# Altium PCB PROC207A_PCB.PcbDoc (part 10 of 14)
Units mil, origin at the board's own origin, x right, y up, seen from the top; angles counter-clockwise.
Board outline 4094.49 x 3724.79 mil, 8 copper layers (Top Layer, L2_GND1, L3_SIG1, L4_PWR1, L5_PWR2, L6_SIG2, L7_GND2, Bottom Layer), stack 58.1 mil thick; 584 components, 399 nets, 8440 pads, 5258 vias.
Unrouted connection lines stored in the file: 9.
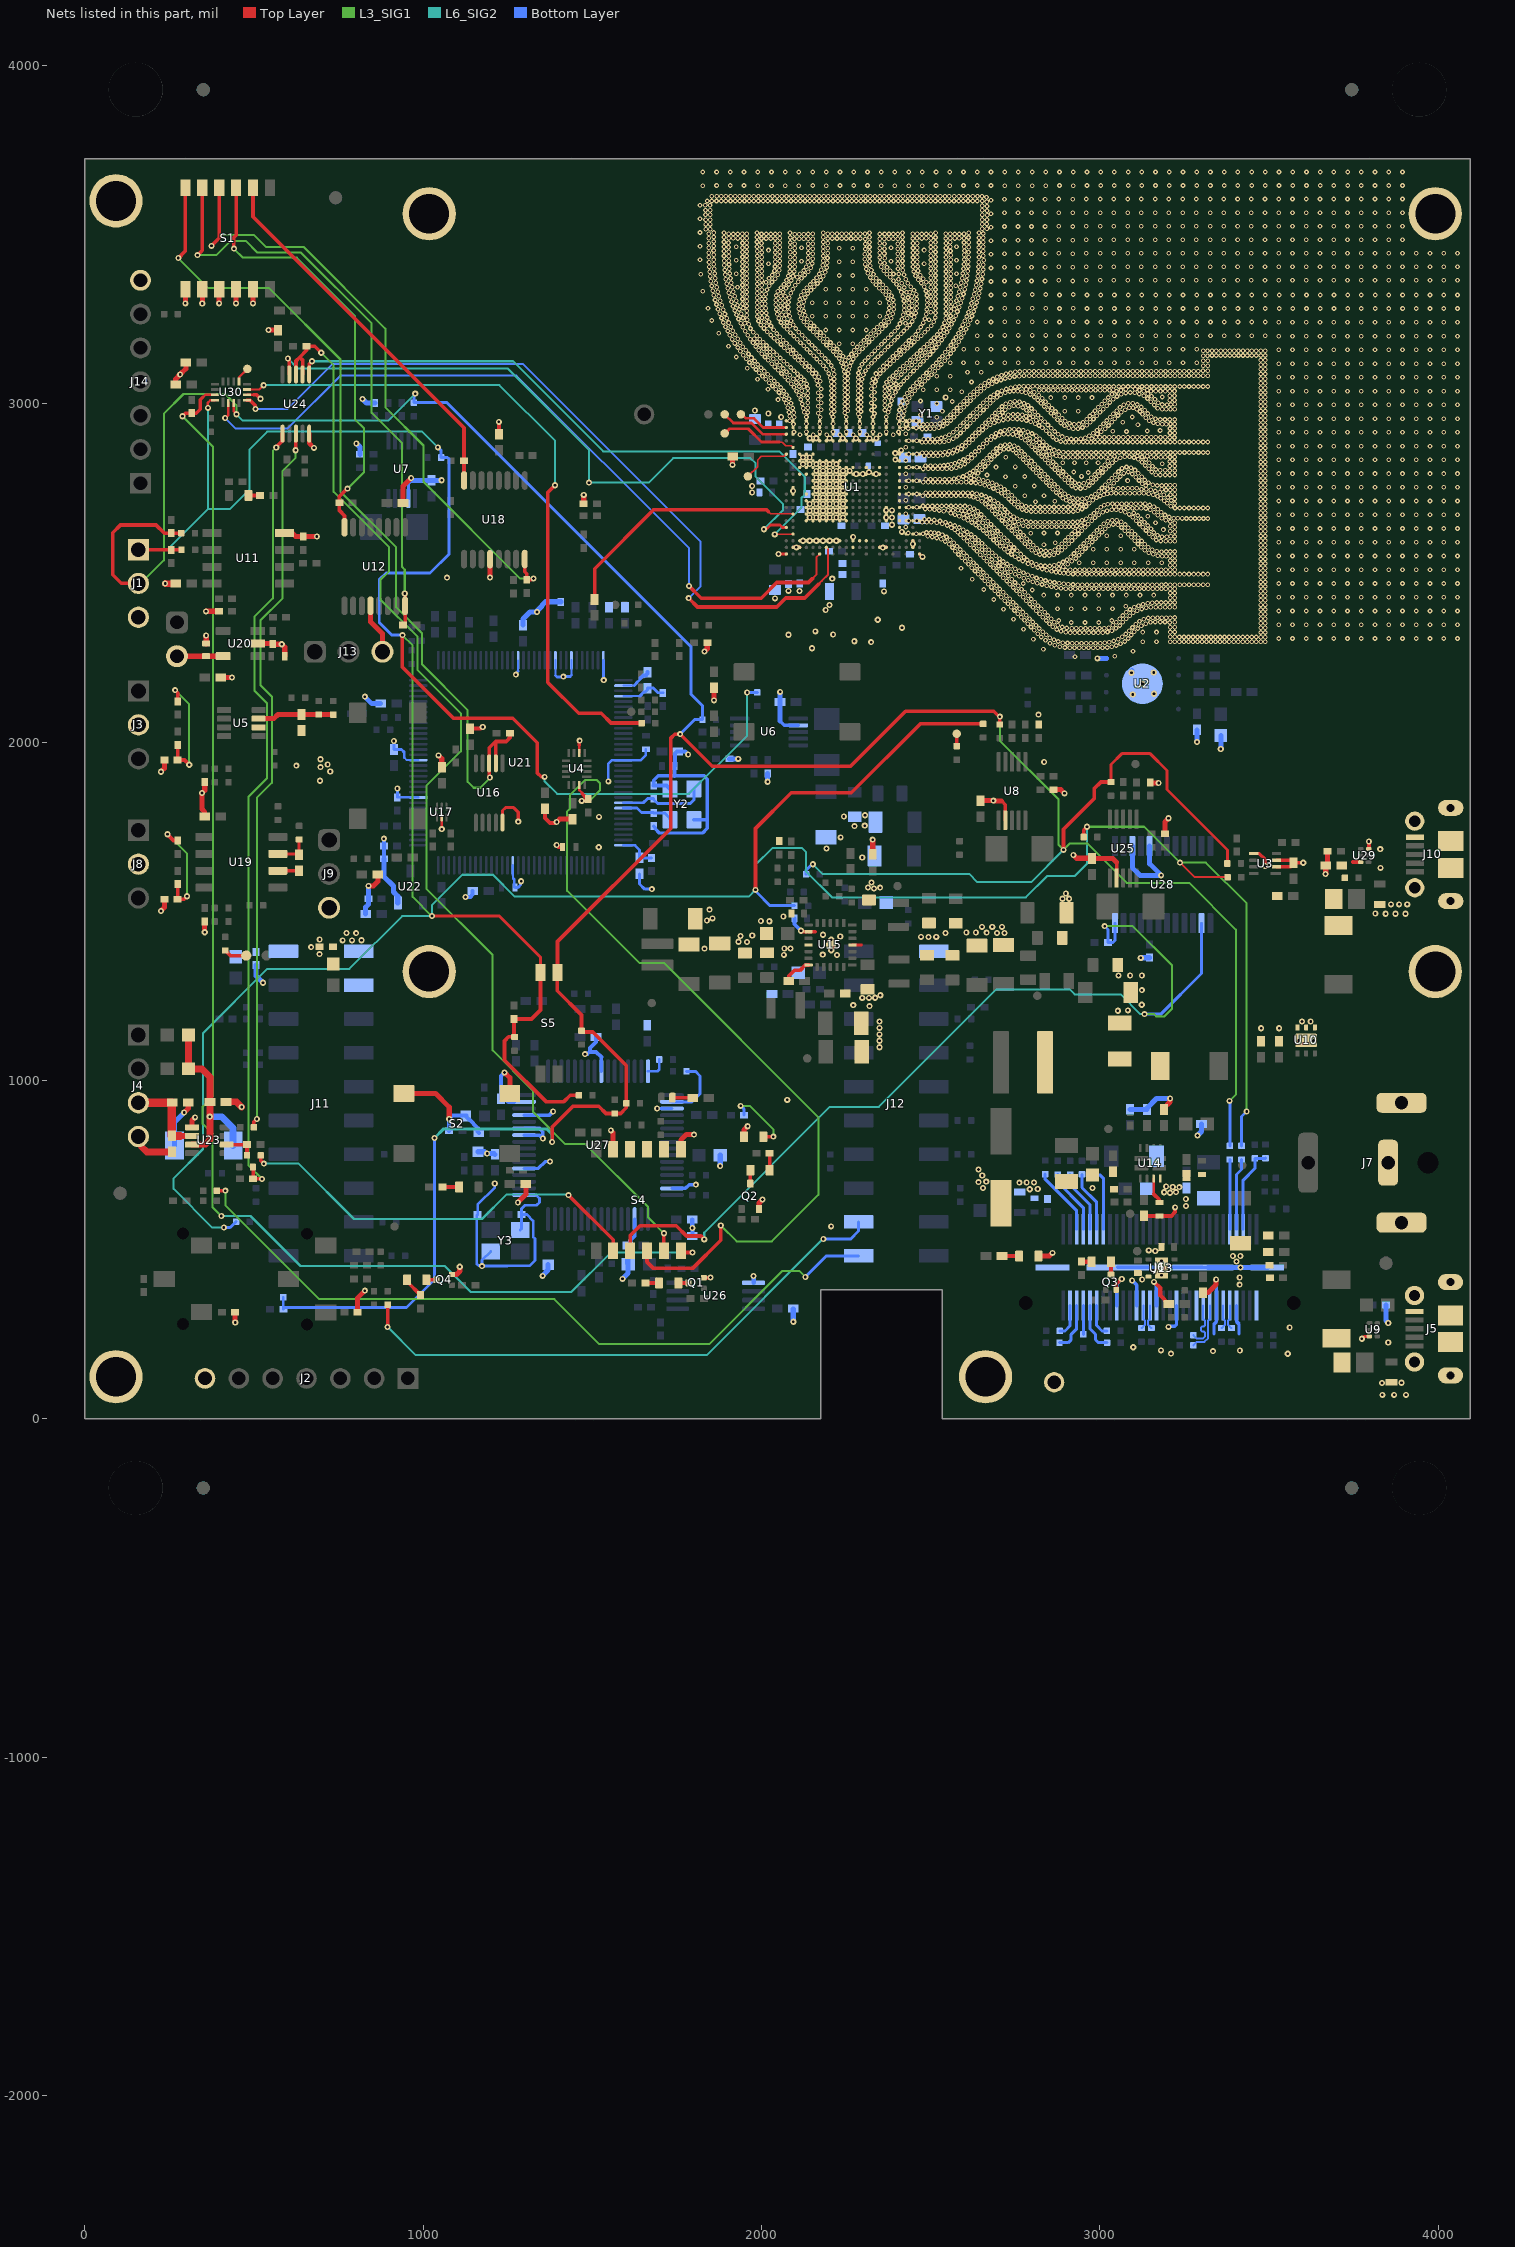
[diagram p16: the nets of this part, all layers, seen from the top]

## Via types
v1: diameter 13.77, hole 7, Top Layer to L2_GND1, tented top, 4306 vias
v2: diameter 18, hole 8, Top Layer to Bottom Layer, tented both sides, 946 vias
v3: diameter 19.68, hole 8, Top Layer to Bottom Layer, tented both sides, 6 vias

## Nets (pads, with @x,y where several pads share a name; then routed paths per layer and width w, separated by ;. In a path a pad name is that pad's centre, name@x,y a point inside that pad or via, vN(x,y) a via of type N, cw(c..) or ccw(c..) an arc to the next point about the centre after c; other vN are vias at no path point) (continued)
GND: (continued)
  other v1: 3043.26,3242.15 3083.82,3242.15 3124.38,3242.15 3164.94,3242.15 3205.5,3242.15 3246.06,3242.15 3286.63,3242.15 3327.19,3242.15 3367.75,3242.15 3408.31,3242.15 3448.87,3242.15 3489.43,3242.15 2008.19,3242.88 2021.96,3242.86 2124.51,3243.17 2509.05,3242.73 2718.78,3242.92 2759.34,3242.92 2799.9,3242.92 2840.46,3242.92 2921.58,3242.92 2445.34,3243.84 1990.94,3245.13 2362.71,3246.07 2601.14,3246.03 1853.32,3246.73 2087.15,3246.51 2554.57,3246.74 2616.75,3247.02 2567.88,3248.12 1957.99,3248.69 2135.61,3250.03 2415.43,3250.12 2495.03,3249.33 1931.85,3251.09 2066.74,3251.47 1897.13,3253.27 2051.08,3252.9 2483.23,3252.32 1881.57,3254.14 1945.13,3254.25 2383.17,3253.71 2431.08,3253.57 2544.22,3253.89 2001.51,3254.87 2117.42,3254.97 2016.92,3255.68 2451.83,3255.98 2513.52,3255.76 2369.75,3257.86 1987.48,3258.46 2149.63,3259.05 2189.63,3259.05 2229.63,3259.05 2269.63,3259.05 2309.63,3259.05 2349.63,3259.05 2606.41,3258.75 2082.95,3259.63 2558.77,3260.22 2622.09,3259.92 2573.87,3260.52 1956.22,3262.27 2129.36,3262.04 2419.43,3263.3 2443.26,3263.21 1926.12,3263.61 2059.71,3263.51 2071.52,3263.88 1891.86,3265.99 2046.24,3265.79 2486.74,3265.64 1876.26,3266.98 1939.72,3266.75 2388.28,3266.5 2112.57,3267.86 2545.28,3267.62 2000.26,3268.88 2013.71,3269.07 2433.23,3268.81 2456.03,3269.1 2374.87,3270.22 2514.35,3269.5 2499.97,3270.89 1986.92,3272.22 2611.68,3271.48 2080.06,3273.09 2579.14,3273.24 2627.39,3273.29 2124.4,3274.9 2559.32,3274.51 1955.99,3276.04 1920.85,3276.33 2056.81,3277 2421.58,3276.9 2444.46,3277 1886.59,3278.71 2043.25,3279.24 2488.93,3279.23 1934.39,3279.44 2391.01,3280 2570.18,3279.7 1871.3,3280.39 2068.77,3280.44 2110.13,3281.41 2545.28,3281.39 2678.22,3282.15 2881.02,3282.15 2962.14,3282.15 3002.7,3282.15 3043.26,3282.15 3083.82,3282.15 3124.38,3282.15 3164.94,3282.15 3205.5,3282.15 3246.06,3282.15 3286.63,3282.15 3327.19,3282.15 3367.75,3282.15 3408.31,3282.15 3448.87,3282.15 3489.43,3282.15 3529.99,3282.15 3570.55,3282.1 3611.11,3282.1 3651.67,3282.1 3692.23,3282.1 3732.79,3282.1 3773.35,3282.1 3813.91,3282.1 3854.47,3282.1 3895.03,3282.1 3935.59,3282.1 3976.16,3282.1 4016.72,3282.1 4057.28,3282.1 1841.72,3282.52 2000.26,3282.64 2012.06,3282.74 2458.35,3282.67 2514.35,3283.27 2718.78,3283.18 2759.34,3283.18 2799.9,3283.18 2840.46,3283.18 2921.58,3283.18 1946.26,3283.86 2377.67,3283.77 2436.01,3284.02 2616.6,3284.34 1986.92,3285.99 2584.41,3285.96 2078.71,3286.79 2632.06,3286.68 2559.32,3288.28 1915.58,3289.05 2122.08,3288.39 1955.99,3289.81 2500.31,3290.16 2055.95,3290.79 2422.44,3290.64 2445.32,3290.79 1882.32,3291.8 1929.15,3292.2 2067.87,3291.91 2572.71,3291.98 2042.32,3292.97 2489.87,3292.97 1866.88,3294.08 2391.25,3293.77 2110.16,3295.18 2545.28,3295.16 1943.81,3296.74 2000.26,3296.41 2011.4,3296.49 2458.95,3296.43 2514.35,3297.04 2377.88,3297.42 2620.74,3297.47 2588.98,3298.95 1986.92,3299.76 2149.63,3299.31 2189.63,3299.31 2229.63,3299.31 2269.63,3299.31 2309.63,3299.31 2349.63,3299.31 2435.59,3299.77 2636.27,3300.05 2079.8,3300.52 1911.28,3302.14 2124.62,3301.95 2559.32,3302.05 1955.99,3303.58 2500.31,3303.93 1878.17,3304.93 2055.89,3304.69 2421.09,3304.34 2445.38,3304.69 1924.99,3305.47 2068.77,3305.36 2576.28,3305.47 1862.72,3307.29 2042.32,3306.74 2489.87,3306.74 2389.01,3307.35 2112.67,3308.72 2545.28,3308.93 2000.26,3310.18 2011.4,3310.26 2458.95,3310.2 1943.81,3310.51 2373.88,3310.94 2514.35,3310.81 2624.88,3310.6 2593.12,3312.08 1986.92,3313.53 2082.18,3314.08 2640.34,3313.84 1907.14,3315.27 2129.27,3314.71 2433.03,3314.87 2559.32,3315.82 1874.05,3318.07 1955.99,3317.35 2417.98,3317.76 2500.31,3317.7 1920.69,3318.72 2056.85,3318.54 2070.38,3318.9 2444.42,3318.54 2580.58,3318.72 1858.99,3321.14 2043.17,3320.49 2384.37,3320.32 2489.1,3320.49 2117.58,3321.58 2678.22,3322.15 2881.02,3322.15 2962.14,3322.15 3002.7,3322.15 3043.26,3322.15 3083.82,3322.15 3124.38,3322.15 3164.94,3322.15 3205.5,3322.15 3246.06,3322.15 3286.63,3322.15 3327.19,3322.15 3367.75,3322.15 3408.31,3322.15 3448.87,3322.15 3489.43,3322.15 3529.99,3322.15 3570.55,3322.1 3611.11,3322.1 3651.67,3322.1 3692.23,3322.1 3732.79,3322.1 3773.35,3322.1 3813.91,3322.1 3854.47,3322.1 3895.03,3322.1 3935.59,3322.1 3976.16,3322.1 4016.72,3322.1 4057.28,3322.1 2367.29,3322.69 2545.28,3322.7 1943.81,3324.28 2000.26,3323.95 2012.63,3323.98 2457.25,3323.86 2628.56,3323.87 2718.78,3323.44 2759.34,3323.44 2799.9,3323.44 2840.46,3323.44 2921.58,3323.44 2514.35,3324.58 2597.26,3325.21 1986.92,3327.3 2086.18,3327.26 2136.69,3326.56 2643.76,3327.56 1903.18,3328.46 2428.64,3329.82 2559.32,3329.59 1955.99,3331.12 2063.55,3330.73 2413.61,3330.81 2437.72,3330.73 1871.02,3331.5 1916.49,3331.73 2377.46,3332.23 2500.31,3331.47 2584.78,3331.73 2048.52,3333.18 2358.43,3333.02 1826.6,3333.69 2124.73,3333.35 2486.32,3333.98 1855.83,3335.16 2450.63,3335.94 2016.3,3337.25 2146.18,3336.71 2545.28,3336.47 1943.81,3338.05 2000.26,3337.71 2631.54,3337.32 2514.35,3338.35 2600.35,3338.63 2092.35,3339.57 2189.63,3339.57 2229.63,3339.57 2269.63,3339.57 2309.63,3339.57 1986.92,3341.07 2646.8,3341.3 1900.2,3341.9 2072.57,3341.61 2348.35,3342.37 2368.28,3342.49 2407.11,3342.96 2057.69,3343.45 2134.02,3343.52 2422.29,3344.24 2559.32,3343.36 1868.04,3344.95 1913.38,3345.11 1929.15,3344.91 1955.99,3344.89 2500.31,3345.24 2587.89,3345.11 2441.31,3346.08 2155.7,3346.44 2480.83,3346.6 1852.87,3348.67 2022.38,3349.6 2545.28,3350.24 2573.72,3349.35 2099.65,3351.24 2634.52,3350.76 1943.81,3351.82 2000.26,3351.48 2338.3,3352.22 2358.54,3352.23 2514.35,3352.12 2603.33,3352.08 2080.3,3353.23 2143.76,3353.25 2066.49,3354.04 2399.18,3354.21 1986.92,3354.84 1897.22,3355.34 2165.55,3356.04 2649.59,3355.4 2414.13,3357.3 2432.62,3356.76 2559.32,3357.13 2472.67,3357.7 1865.13,3358.41 1910.65,3358.48 1955.99,3358.66 2500.31,3359.01 2590.62,3358.48 2013.39,3360.28 2486.81,3359.37 2030.87,3360.45 2108.53,3361.77 2348.8,3361.96 2678.22,3362.15 1850.41,3362.83 2153.49,3362.99 2329.07,3362.7 2545.28,3364.01 2718.22,3363.7 2758.22,3363.7 2798.22,3363.7 2838.22,3363.7 2919.78,3363.7 2000.26,3365.25 2087.68,3365.18 2390.02,3364.49 2636.92,3364.32 1943.81,3365.59 2073.71,3365.77 2514.35,3365.89 2606.08,3365.57 2879.15,3365.77 2960.4,3365.77 3001.03,3365.77 3041.65,3365.77 3082.28,3365.77 3122.9,3365.77 3163.53,3365.77 3204.15,3365.77 3244.78,3365.77 3285.4,3365.77 3326.03,3365.77 3366.65,3365.77 3407.28,3365.77 3447.9,3365.77 3488.53,3365.77 3529.15,3365.77 3569.78,3365.77 3610.4,3365.77 3651.03,3365.77 3691.65,3365.77 3732.28,3365.77 3772.9,3365.77 3813.53,3365.77 3854.15,3365.77 3894.78,3365.77 3935.4,3365.77 3976.03,3365.77 4016.65,3365.77 4057.28,3365.77 2174.72,3366.38 2463.28,3367.77 1894.75,3368.89 1986.92,3368.61 2404.8,3368.99 2425.94,3368.8 2651.74,3369.31 2022.14,3371.22 2040.25,3370.52 2477.6,3370.55 2559.32,3370.9 1863.33,3372.06 1908.23,3372.1 1955.99,3371.81 2118.27,3371.5 2339.42,3372.04 2593.04,3372.1 2162.77,3373.17 2500.31,3372.78 2321.03,3373.75 2380.28,3374.23 2105.19,3374.65 1848.51,3377.05 2093.09,3378.12 2182.89,3377.47 2545.28,3377.78 2638.72,3377.97 2000.26,3379.02 2079.25,3378.38 2455.34,3379.02 2607.88,3379.22 1943.81,3379.36 2229.63,3379.83 2269.63,3379.83 2514.35,3379.66 2128.01,3381.24 2468.74,3380.93 2031.7,3381.44 2047.62,3382.16 2421.03,3381.66 1892.95,3382.54 1986.92,3382.38 2331.2,3383.09 1820.54,3383.87 2370.54,3383.96 2390.29,3384.07 2406.08,3384.28 2653.57,3383.32 1924.92,3384.59 1955.99,3384.96 2114.76,3384.9 2170.76,3384.38 2559.32,3384.67 2576.35,3384.59 1861.54,3385.71 1906.46,3385.84 2314.45,3386 2594.81,3385.84 2500.31,3386.55 2188.81,3389.93 1846.79,3390.81 2137.68,3391.04 2083.01,3391.62 2096.82,3391.63 2450.09,3391.75 2545.28,3391.55 2640.51,3391.62 1943.81,3393.13 2000.26,3392.78 2609.68,3392.87 2038.48,3393.33 2361.14,3394.03 2380.31,3394.01 2462.79,3393.33 2514.35,3393.43 2052.21,3395.14 2124.41,3394.63 2417.92,3395.08 1891.16,3396.19 1986.92,3396.15 2324.91,3395.34 2176.8,3396.76 1955.99,3398.11 2655.07,3397.62 2309.38,3398.94 2559.32,3398.44 1859.92,3399.39 1904.65,3399.55 2403.49,3399.74 2597.2,3399.45 2500.31,3400.32 2678.22,3402.15 2145.52,3402.36 2193.14,3403.62 2370.85,3404.18 2718.22,3403.96 2758.22,3403.96 2798.22,3403.96 2838.22,3403.96 2919.78,3403.96 1845.63,3405.13 2098.24,3405.19 2084.36,3405.32 2132.35,3406.08 2353.93,3405.76 2447.79,3405.32 2545.28,3405.32 2641.61,3405.35 2879.15,3405.77 2960.4,3405.77 3001.03,3405.77 3041.65,3405.77 3082.28,3405.77 3122.9,3405.77 3163.53,3405.77 3204.15,3405.77 3244.78,3405.77 3285.4,3405.77 3326.03,3405.77 3366.65,3405.77 3407.28,3405.77 3447.9,3405.77 3488.53,3405.77 3529.15,3405.77 3569.78,3405.77 3610.4,3405.77 3651.03,3405.77 3691.65,3405.77 3732.28,3405.77 3772.9,3405.77 3813.53,3405.77 3854.15,3405.77 3894.78,3405.77 3935.4,3405.77 3976.03,3405.77 4016.65,3405.77 4057.28,3405.77 1943.81,3406.9 2000.26,3406.55 2039.87,3406.46 2461.4,3406.46 2514.35,3407.2 2610.9,3406.59 2053.63,3408.84 2320.91,3408.51 2416.72,3408.8 1890.22,3409.93 1986.92,3409.92 2180.59,3410 1955.99,3411.26 2559.32,3412.21 2655.94,3411.62 1859.32,3413.14 1903.78,3412.33 2306.44,3412.52 2500.31,3413.06 2598.66,3413.11 2020.73,3414.72 2150.29,3415.28 2402.7,3415.07 2480.54,3414.72 2363.59,3415.86 2194.77,3417.5 2084.55,3419.09 2098.24,3418.95 2137.02,3418.87 2350.54,3419.1 2447.64,3419.09 2642.21,3419.11 1844.99,3419.41 2040.64,3420.29 2229.63,3420.09 2269.63,3420.09 2460.63,3420.29 2545.28,3419.32 1943.81,3420.67 2000.26,3420.32 2514.35,3420.97 2611.5,3420.35 2118.38,3421.63 2319.35,3422.19 2382.89,3421.63 2053.63,3422.61 2416.72,3422.76 1889.62,3423.69 1902.95,3423.87 1986.92,3423.69 2182.07,3423.69 1924.92,3424.85 1955.99,3424.41 2576.35,3424.85 2656.55,3424.88 2500.31,3425.81 2559.32,3425.98 1818.25,3426.35 1858.72,3426.9 2599.24,3427.02 2305.22,3428.15 2151.26,3429.01 2402.68,3429.66 2363.83,3430.33 2194.99,3431.55 1844.5,3433.29 2098.24,3432.72 2137.75,3432.45 2350.01,3432.86 2447.64,3433.13 2000.26,3434.09 2040.64,3434.05 2084.55,3433.67 2460.63,3434.05 2545.28,3433.32 2612.1,3434.1 2642.82,3433.62 1943.81,3434.44 2514.35,3434.74 2319.08,3435.96 1903.12,3437.01 2053.59,3436.38 2416.72,3436.72 1889.28,3437.46 1955.99,3437.56 1986.92,3437.46 2182.19,3437.46 2655.97,3438.14 2500.31,3438.56 2559.22,3439.66 1858.35,3440.66 2599.73,3440.85 2678.22,3442.15 2305.04,3443.07 2151.26,3443.84 2402.68,3444.25 2718.22,3444.22 2758.22,3444.22 2798.22,3444.22 2838.22,3444.22 2919.78,3444.22 2363.34,3444.79 2137.94,3446.15 2195.5,3445.93 2879.15,3445.77 2960.4,3445.77 3001.03,3445.77 3041.65,3445.77 3082.28,3445.77 3122.9,3445.77 3163.53,3445.77 3204.15,3445.77 3244.78,3445.77 3285.4,3445.77 3326.03,3445.77 3366.65,3445.77 3407.28,3445.77 3447.9,3445.77 3488.53,3445.77 3529.15,3445.77 3569.78,3445.77 3610.4,3445.77 3651.03,3445.77 3691.65,3445.77 3732.28,3445.77 3772.9,3445.77 3813.53,3445.77 3854.15,3445.77 3894.78,3445.77 3935.4,3445.77 3976.03,3445.77 4016.65,3445.77 4057.28,3445.77 2098.24,3446.48 2350.01,3446.81 2447.64,3447.16 1844.31,3447.36 1943.81,3448.21 2000.26,3447.86 2040.64,3447.82 2084.55,3448.24 2460.63,3447.82 2545.28,3447.31 2642.92,3448.14 2514.35,3449.1 2611.99,3448.59 1902.81,3450.14 2053.59,3449.66 2319.08,3450.08 1889.28,3451.23 1955.99,3450.71 1986.92,3451.23 2182.19,3451.23 2416.72,3450.68 2500.31,3451.3 2655.97,3451.41 2558.7,3452.34 2599.97,3453.02 1858.27,3453.87 2020.73,3454.98 2480.54,3454.98 2306.78,3458 2151.26,3458.67 2363.55,3459.24 2402.68,3458.84 2098.24,3460.25 2137.94,3459.92 2195.5,3460.3 2229.63,3460.35 2269.63,3460.35 2350.01,3460.76 2447.64,3461.2 1844.12,3461.44 1943.81,3461.98 2000.26,3461.63 2040.64,3461.59 2118.38,3461.89 2382.89,3461.89 2460.63,3461.59 2545.28,3461.31 1902.39,3463.28 2053.59,3462.95 2084.55,3462.81 2612.29,3463.08 2642.57,3462.66 1956.33,3463.86 2319.08,3464.19 2500.31,3464.05 2514.35,3463.46 1889.27,3465.05 1924.92,3465.11 1986.57,3464.99 2182.19,3465 2416.72,3464.65 2558.13,3465.01 2576.35,3465.11 2599.5,3465.2 2655.97,3464.67 1818.25,3466.61 1858.35,3467.08 2306.78,3472.93 2097.89,3474.02 2137.94,3473.69 2151.26,3473.5 2363.75,3473.7 2402.68,3473.43 2195.5,3474.68 2350.01,3474.71 2447.64,3475.23 1843.94,3475.51 1943.81,3475.75 1999.91,3475.39 2040.64,3475.36 2053.59,3476.23 2460.63,3475.36 2545.28,3475.31 1902.53,3476.41 1956.33,3477 2500.69,3476.8 2642.79,3477.18 2084.55,3477.39 2514.35,3477.82 2557.9,3477.69 2598.38,3477.37 2612.35,3477.56 2655.97,3477.93 1889.27,3478.88 1986.57,3478.76 2182.19,3478.77 2319.08,3478.31 2416.72,3478.61 1858.35,3480.29 2678.22,3482.15 2718.22,3484.47 2758.22,3484.47 2798.22,3484.47 2838.22,3484.47 2919.78,3484.47 2879.15,3485.77 2960.4,3485.77 3001.03,3485.77 3041.65,3485.77 3082.28,3485.77 3122.9,3485.77 3163.53,3485.77 3204.15,3485.77 3244.78,3485.77 3285.4,3485.77 3326.03,3485.77 3366.65,3485.77 3407.28,3485.77 3447.9,3485.77 3488.53,3485.77 3529.15,3485.77 3569.78,3485.77 3610.4,3485.77 3651.03,3485.77 3691.65,3485.77 3732.28,3485.77 3772.9,3485.77 3813.53,3485.77 3854.15,3485.77 3894.78,3485.77 2097.56,3488.07 2111.19,3488.22 2306.78,3487.86 2363.34,3488.16 2376.45,3488.02 2389.57,3488.02 2402.68,3488.02 1999.91,3489.16 2013.49,3489.2 2027.06,3489.16 2040.64,3489.12 2124.54,3488.41 2137.89,3488.6 2151.36,3488.33 2195.5,3489.05 2209.27,3489.05 2223.04,3489.05 2236.81,3489.05 2250.58,3489.05 2264.35,3489.05 2278.12,3489.05 2291.89,3489.05 2350.01,3488.66 2447.3,3489.27 2544.94,3489.3 1843.75,3489.58 1902.81,3489.54 1916.66,3489.41 1930.24,3489.38 1943.81,3489.52 1956.33,3490.15 2053.59,3489.52 2459.82,3489.52 2473.39,3489.38 2486.97,3489.41 2500.82,3489.54 2557.46,3489.52 2571.03,3489.37 2584.61,3489.41 2598.46,3489.54 2655.97,3491.2 2084.55,3491.96 2514.36,3492.18 2612,3492.05 2642.79,3491.7 1889.27,3492.71 1986.57,3492.53 2182.19,3492.54 2319.08,3492.42 2416.72,3492.57 1858.35,3493.5 2098.08,3502.15 2111.35,3501.99 2124.62,3502.18 1902.85,3502.68 1916.43,3502.64 1930,3502.6 1943.58,3502.74 1956.33,3503.3 2000.15,3502.38 2013.72,3502.42 2026.83,3502.38 2040.4,3502.34 2053.59,3502.8 2137.89,3502.37 2151.2,3503.16 2195.5,3502.82 2209.27,3502.82 2223.04,3502.82 2236.81,3502.82 2250.58,3502.82 2264.35,3502.82 2278.12,3502.82 2291.89,3502.82 2305.78,3502.79 2350.01,3502.61 2363.78,3502.61 2376.74,3502.61 2389.71,3502.61 2402.68,3502.61 2447.3,3503.3 2460.05,3502.74 2473.63,3502.6 2487.21,3502.64 2500.78,3502.68 2544.94,3503.3 2557.69,3502.74 2571.27,3502.6 2584.84,3502.64 2598.42,3502.67 1843.56,3503.66 2655.97,3503.91 2642.79,3506.22 1818.25,3506.87 1858.52,3506.71 1889.11,3506.54 1986.58,3506.54 2084.38,3506.54 2182.19,3506.54 2319.08,3506.54 2416.72,3506.54 2514.53,3506.54 2612.16,3506.54 1835.01,3516.68 1848.78,3516.68 2652.73,3517.54 2666.35,3517.93 2678.22,3522.15 2718.22,3524.73 2758.22,3524.73 2798.22,3524.73 2838.22,3524.73 2919.78,3524.73 2879.15,3525.77 2960.4,3525.77 3001.03,3525.77 3041.65,3525.77 3082.28,3525.77 3122.9,3525.77 3163.53,3525.77 3204.15,3525.77 3244.78,3525.77 3285.4,3525.77 3326.03,3525.77 3366.65,3525.77 3407.28,3525.77 3447.9,3525.77 3488.53,3525.77 3529.15,3525.77 3569.78,3525.77 3610.4,3525.77 3651.03,3525.77 3691.65,3525.77 3732.28,3525.77 3772.9,3525.77 3813.53,3525.77 3854.15,3525.77 3894.78,3525.77 1834.82,3530.76 1848.59,3530.76 2652.73,3531.31 2666.12,3532 1834.63,3544.83 1848.4,3544.83 2652.73,3545.08 2666.5,3545.08 1818.25,3547.13 2666.87,3558.15 1834.44,3558.91 1848.21,3558.91 2652.73,3558.85 2678.22,3562.15 2718.22,3564.99 2758.22,3564.99 2798.22,3564.99 2838.22,3564.99 2919.78,3564.99 2879.15,3565.77 2960.4,3565.77 3001.03,3565.77 3041.65,3565.77 3082.28,3565.77 3122.9,3565.77 3163.53,3565.77 3204.15,3565.77 3244.78,3565.77 3285.4,3565.77 3326.03,3565.77 3366.65,3565.77 3407.28,3565.77 3447.9,3565.77 3488.53,3565.77 3529.15,3565.77 3569.78,3565.77 3610.4,3565.77 3651.03,3565.77 3691.65,3565.77 3732.28,3565.77 3772.9,3565.77 3813.53,3565.77 3854.15,3565.77 3894.78,3565.77 2666.69,3571.23 1834.25,3572.98 1848.03,3572.98 2652.73,3572.62 2666.5,3584.3 1834.07,3587.05 1847.84,3587.05 2652.73,3586.39 1818.25,3587.39 2666.3,3597.38 1839.29,3600.18 1853.17,3600.16 1866.94,3600.16 1880.71,3600.16 1894.48,3600.16 1908.25,3600.16 1922.02,3600.16 1935.79,3600.16 1949.56,3600.16 1963.33,3600.16 1977.1,3600.16 1990.87,3600.16 2004.64,3600.16 2018.41,3600.16 2032.18,3600.16 2045.95,3600.16 2059.72,3600.16 2073.49,3600.16 2087.26,3600.16 2101.03,3600.16 2114.8,3600.16 2128.57,3600.16 2142.34,3600.16 2156.11,3600.16 2169.88,3600.16 2183.65,3600.16 2197.42,3600.16 2211.19,3600.16 2224.96,3600.16 2238.73,3600.16 2252.5,3600.16 2266.27,3600.16 2280.04,3600.16 2293.81,3600.16 2307.58,3600.16 2321.35,3600.16 2335.12,3600.16 2348.89,3600.16 2362.66,3600.16 2376.43,3600.16 2390.2,3600.16 2403.97,3600.16 2417.74,3600.16 2431.51,3600.16 2445.28,3600.16 2459.05,3600.16 2472.82,3600.16 2486.59,3600.16 2500.36,3600.16 2514.13,3600.16 2527.9,3600.16 2541.67,3600.16 2555.44,3600.16 2569.21,3600.16 2582.98,3600.16 2596.75,3600.16 2610.52,3600.16 2624.29,3600.16 2638.06,3600.16 2652.73,3600.16 2678.22,3602.15 2718.22,3605.25 2758.22,3605.25 2798.22,3605.25 2838.22,3605.25 2919.78,3605.25 2879.15,3605.77 2960.4,3605.77 3001.03,3605.77 3041.65,3605.77 3082.28,3605.77 3122.9,3605.77 3163.53,3605.77 3204.15,3605.77 3244.78,3605.77 3285.4,3605.77 3326.03,3605.77 3366.65,3605.77 3407.28,3605.77 3447.9,3605.77 3488.53,3605.77 3529.15,3605.77 3569.78,3605.77 3610.4,3605.77 3651.03,3605.77 3691.65,3605.77 3732.28,3605.77 3772.9,3605.77 3813.53,3605.77 3854.15,3605.77 3894.78,3605.77 2665.17,3610.97 1853.17,3613.93 1867.24,3614.12 1894.48,3613.93 1908.55,3614.12 1935.79,3613.93 1949.86,3614.12 1977.1,3613.93 1991.17,3614.12 2018.41,3613.93 2032.48,3614.12 2059.72,3613.93 2073.79,3614.12 2101.03,3613.93 2115.1,3614.12 2142.34,3613.93 2156.41,3614.12 2183.65,3613.93 2197.72,3614.12 2224.96,3613.93 2239.03,3614.12 2266.27,3613.93 2280.34,3614.12 2307.58,3613.93 2321.35,3613.93 2335.42,3614.12 2362.66,3613.93 2376.73,3614.12 2403.97,3613.93 2417.74,3613.93 2431.81,3614.12 2459.05,3613.93 2473.12,3614.12 2500.36,3613.93 2514.13,3613.93 2528.2,3614.12 2555.44,3613.93 2569.51,3614.12 2596.75,3613.93 2610.52,3613.93 2624.59,3614.12 2651.83,3613.93 1881.31,3614.31 1922.62,3614.31 1963.93,3614.31 2005.24,3614.31 2046.55,3614.31 2087.86,3614.31 2129.17,3614.31 2170.48,3614.31 2211.79,3614.31 2253.1,3614.31 2294.41,3614.31 2349.49,3614.31 2390.8,3614.31 2445.88,3614.31 2487.19,3614.31 2542.27,3614.31 2583.58,3614.31 2638.66,3614.31 1826.62,3645.51 1867.17,3645.77 1907.73,3645.77 1948.28,3645.77 1988.83,3645.51 2029.38,3645.51 2069.93,3645.51 2110.49,3645.51 2151.04,3645.77 2191.59,3645.51 2232.14,3645.77 2272.7,3645.77 2313.25,3645.77 2353.8,3645.51 2394.35,3645.51 2434.9,3645.51 2475.46,3645.51 2516.01,3645.77 2556.56,3645.51 2597.11,3645.77 2637.66,3645.77 2678.22,3645.77 2718.77,3645.51 2759.32,3645.51 2799.87,3645.51 2840.42,3645.51 2880.98,3645.77 2921.53,3645.51 2962.08,3645.77 3002.63,3645.77 3043.18,3645.77 3083.74,3645.77 3124.29,3645.77 3164.84,3645.77 3205.39,3645.77 3245.95,3645.77 3286.5,3645.77 3327.05,3645.77 3367.6,3645.77 3408.15,3645.77 3448.71,3645.77 3489.26,3645.77 3529.81,3645.77 3570.36,3645.77 3610.91,3645.77 3651.47,3645.77 3692.02,3645.77 3732.57,3645.77 3773.12,3645.77 3813.67,3645.77 3854.23,3645.77 3894.78,3645.77 1826.62,3685.77 1867.17,3685.77 1907.73,3685.77 1948.28,3685.77 1988.83,3685.77 2029.38,3685.77 2069.93,3685.77 2110.49,3685.77 2151.04,3685.77 2191.59,3685.77 2232.14,3685.77 2272.7,3685.77 2313.25,3685.77 2353.8,3685.77 2394.35,3685.77 2434.9,3685.77 2475.46,3685.77 2516.01,3685.77 2556.56,3685.77 2597.11,3685.77 2637.66,3685.77 2678.22,3685.77 2718.77,3685.77 2759.32,3685.77 2799.87,3685.77 2840.42,3685.77 2880.98,3685.77 2921.53,3685.77 2962.08,3685.77 3002.63,3685.77 3043.18,3685.77 3083.74,3685.77 3124.29,3685.77 3164.84,3685.77 3205.39,3685.77 3245.95,3685.77 3286.5,3685.77 3327.05,3685.77 3367.6,3685.77 3408.15,3685.77 3448.71,3685.77 3489.26,3685.77 3529.81,3685.77 3570.36,3685.77 3610.91,3685.77 3651.47,3685.77 3692.02,3685.77 3732.57,3685.77 3773.12,3685.77 3813.67,3685.77 3854.23,3685.77 3894.78,3685.77
  other v2: 3835.18,71 3870.18,71 3905.18,71 3833.95,106.13 3891.85,106.65 3210.27,192.64 3555.64,192.51 3334.58,200.01 3413.89,202.24 3180.79,202.6 3098.95,211.6 3852.82,225.73 3561.23,269.7 2094.08,286.89 3413.53,396.67 3125.15,411.83 3413.53,417.69 3404.24,465.32 3393.28,481.46 3415.36,481.46 3163.96,495.9 3144.72,497.95 2206,569 3255.09,629.12 3254.34,649.72 3207.59,668.28 3190.15,669.81 3225.31,670.1 2792.98,678.69 2816.58,679.21 2654.96,682.46 2978.67,682.41 3235.18,684.85 3215.64,685.33 3196.17,686.75 2762.15,698.23 2783.69,698.52 2805.24,698.52 2641.54,699.58 2664.38,701 2652.51,719.18 2641.29,736.93 1800.19,840.19 1384.17,908.3 2076,943 2348.9,1098.57 2348.9,1117.61 2348.9,1136.65 3477.09,1154.52 3530.18,1154.52 2348.9,1155.7 2348.9,1174.74 3597.48,1174.52 3623.45,1174.52 3053.37,1206.31 3082.77,1207.52 2318.96,1219.87 2271.13,1222.95 3123.89,1223.95 2297.9,1244.37 2317.45,1244.37 2335.79,1244.77 2351.43,1252.16 3124.24,1267.29 3055.3,1310.62 3089.77,1310.62 3124.24,1310.62 2066.11,1371.5 2181.07,1372.07 2223.21,1371.43 693.2,1373.55 1831.27,1389.78 2085.67,1390.05 2067.49,1390.56 668.6,1394.31 1957.19,1409.47 1931.78,1410.36 693.77,1417.03 2471.72,1424.73 2493.43,1424.42 2516.53,1424.67 2232.78,1425.82 1937.73,1427.35 1972.5,1428.58 2181.47,1431.09 2544.11,1436.23 2696.05,1436.14 2718.13,1435.88 2665.46,1437.05 2605.39,1437.85 2633.71,1437.85 2651.68,1454.45 2682.12,1454.45 2710.66,1454.45 2023.18,1471.02 1997.92,1471.74 1838.27,1473.01 1855.01,1479.61 2064.46,1484.91 3845,1493 3874.2,1493.04 3903.4,1493.08 3814.4,1493.91 224.58,1501.17 1846.44,1505.23 3861.07,1521 3885,1521 3908.93,1521 2889.93,1537.42 2909.46,1537.42 2899.7,1552.93 2332.74,1567.89 2350.59,1570.18 2314.74,1570.62 2325.13,1585.32 3829.95,1628.72 2297.77,1659.35 3829.12,1684 2192,1686 1518.85,1689.79 2234,1719 2274.98,1752.07 2305.18,1753.42 3203.12,1775.49 1519.49,1779.4 2243.53,1780.7 2306.15,1784.36 2685.3,1827.29 3174.03,1879.65 695.14,1886.32 224.75,1912.88 725.14,1913.47 696.14,1926.32 624.89,1930.93 717.5,1934.3 2835.39,1941.94 696.27,1949.79 2818.54,2081.72 3097.49,2141.47 3160.48,2143.44 3126,2173 3159.5,2206.43 2149.52,2277.97 2324.23,2295.93 2274.35,2298.52 2079.93,2317.73 2211.63,2318.36 2159.15,2327.94 2415.59,2338.42 2343.68,2362.06 2189.5,2390.79 2201.02,2405.65 2040.04,2425.58 2361.91,2446.22 2079.99,2447.48 2112.51,2447.31 2209.15,2483.73 1070.01,2486.68 2358.63,2575.4 2122.68,2595.77 2142.37,2595.77 2162.05,2595.77 2181.74,2595.77 2201.42,2595.77 2221.11,2595.77 2270.93,2606.92 2414.94,2622.15 2385.74,2642.94 2142.37,2664.66 2162.05,2664.66 2181.74,2664.66 2201.42,2664.66 2221.11,2664.66 2240.79,2664.66 2368.56,2664.38 2385.74,2664.38 2142.37,2684.35 2162.05,2684.35 2181.74,2684.35 2201.42,2684.35 2221.11,2684.35 2240.79,2684.35 2368.56,2685.72 2385.74,2685.72 2142.37,2704.03 2162.05,2704.03 2181.74,2704.03 2201.42,2704.03 2221.11,2704.03 2240.79,2704.03 2162.05,2723.72 2181.74,2723.72 2201.42,2723.72 2221.11,2723.72 2240.79,2723.72 1972.27,2738.46 2093.42,2742.71 2162.05,2743.4 2181.74,2743.4 2201.42,2743.4 2221.11,2743.4 2240.79,2743.4 1972.27,2757.75 2162.05,2763.09 2181.74,2763.09 2201.42,2763.09 2221.11,2763.09 2240.79,2763.09 2162.05,2782.77 2181.74,2782.77 2201.42,2782.77 2221.11,2782.77 2240.79,2782.77 2279.97,2792.82 2299.65,2792.82 2339.02,2792.82 2317.87,2798.56 2162.05,2802.46 2181.74,2802.46 2201.42,2802.46 2221.11,2802.46 2240.79,2802.46 2260.48,2802.46 2122.67,2822.06 2142.35,2822.06 2162.05,2822.14 2181.74,2822.14 2201.42,2822.14 2221.11,2822.14 2395.63,2835.37 2122.67,2841.74 2142.35,2841.74 2395.39,2854.5 2412.83,2862.94 677.27,2870.41 2142.35,2898.66 2162.03,2898.66 2201.2,2898.35 2240.06,2898.32 2279.43,2898.32 2319.31,2898.35 2339.44,2898.35 2428.03,2939.9 2057.99,2961.74 2020.26,2971.9 1980.41,2980.77 2544.44,3019.67 346.89,3297.26 296.73,3297.41 396.73,3297.41 446.73,3297.41 496.73,3297.41
  other v3: 3182.65,424.09 3182.65,467.4 3588.41,1118.68 3631.72,1118.68 2206.22,1384.98 2206.22,1416.56
GPADC1: TP11.1 U1.AA2 | length 150.4
  Top Layer w8: TP11.1@1939.12,2969.15 1942.07,2969.15 1953.65,2957.57 1977.8,2957.57 2004.96,2930.41 U1.AA2@2073.47,2930.41
GPADC2: TP12.1 U1.AA3 | length 206.6
  Top Layer w8: TP12.1@1891.06,2969.15 1916.73,2943.47 1970.69,2943.47 2003.44,2910.73 U1.AA3@2073.47,2910.73
GPADC3: TP5.1 U1.AA6 | length 152.4
  Top Layer w5: TP5.1@1959.66,2785.99 1988.52,2814.85 1988.52,2834.33 1999.6,2845.41 2067.21,2845.41 U1.AA6@2073.47,2851.67
GPADC4: TP6.1 U1.Y5 | length 230.4
  Top Layer w4: 2052.02,2887.46 2061.02,2887.46 2072.17,2876.31 2087.71,2876.31 2092.66,2871.36 U1.Y5@2092.82,2871.36
  Top Layer w8: TP6.1@1891.06,2913 1904.79,2926.73 1960.73,2926.73 2000.01,2887.46 2052.02,2887.46
HARDWARE_TRIGGER: J15.2 R254.1 | length 68.5
  Top Layer w10.8: R254.1@414.56,1384.37 429.5,1369.43 J15.2@476.88,1369.43
HOST_CLK_REQ: TP4.1 U30.9 | length 47.5
  Top Layer w7: U30.9@455.49,3066.34 455.49,3078.91 TP4.1@480.15,3103.58
HOST_CLK_REQ_SPIB_MISO: R270.2 U30.7 | length 2033.1
  Top Layer w7: U30.7@479.37,3042.98 515.53,3042.98 v2@528.05,3055.49
  Top Layer w10.8: v2(1389.72,2759.73) 1368.29,2738.3 1368.29,2176.93 1459.51,2085.71 1526.22,2085.71 1555.17,2056.76 R270.2@1645.51,2056.76
  L6_SIG2 w6: v2(528.37,3055.49) 1224.98,3055.49 1389.72,2890.75 v2(1389.72,2759.73)
HOSTIRQ_FTDI_IN: R216.1 U27.32 | length 64.7
  Bottom Layer w8.7: U27.32@1664.49,1027.56 1692.42,1027.56 1697.76,1032.91 R216.1@1697.76,1062.08
HOSTIRQ_FTDI_OUT: R217.1 U27.34 | length 191
  Bottom Layer w8.7: U27.34@1735.35,937.01 1794.42,937.01 1818.24,960.83 1818.24,1013.65 1804.7,1027.18 1778.57,1027.18 R217.1@1778.47,1027.08
I2C_SCL: J1.1 R25.2 R55.2 R60.1 R89.1 R96.2 R97.1 R108.2 R109.2 R137.2 R159.2 R164.1 R199.1 R224.1 S5.2 U30.16 | length 12372.4
  Top Layer w6: v2(3237.24,1644.24) 3280.34,1601.14 R55.2@3377.77,1601.14
  Top Layer w7: v2(363.51,2988.52) 363.51,3004.42 370.31,3011.22 U30.16@384.62,3011.22
  Top Layer w8.7: v2(1025.69,1486.18) 1224.8,1486.18 1346.54,1364.44 S5.2@1346.54,1319.13
  Top Layer w10.8: J1.1@158.07,2569.5 158.78,2568.79 R97.1@254.77,2568.79 R159.2@285.26,2568.79 ; v2(938.48,2316.6) 938.48,2221.7 1089.42,2070.75 1264.77,2070.75 1337.1,1998.43 1337.1,1909.31 1348.71,1897.69 v2(1359.02,1897.69) ; R199.1@1269.99,1128.63 R199.1@1269.33,1129.3 ; S5.2@1346.54,1319.13 1346.54,1208.38 1320.01,1181.85 R164.1@1268.16,1181.85 1268.16,1130.47 R199.1@1269.33,1129.3 ; R96.2@1460.07,956.46 1434.52,956.46 1415.84,937.78 1362.66,937.78 1240.16,1060.28 1240.16,1117.15 1252.31,1129.3 R199.1@1269.33,1129.3 ; v2(1982.33,1563.88) 1982.33,1745.33 2087.66,1850.66 2265.66,1850.66 2469.31,2054.31 R109.2@2654.96,2054.31 ; R137.2@2952.39,1720.11 2952.39,1740.41 v2(2962.26,1750.28)
  L3_SIG1 w6: v2(938.48,2316.6) 968.5,2286.58 968.5,1543.36 v2(1025.69,1486.18) ; v2(2962.26,1750.28) 3131.2,1750.28 v2(3237.24,1644.24) 3313.76,1644.24 3434.04,1523.96 v2(3434.04,908.41)
  L6_SIG2 w6: J1.1@158.07,2569.5 243.71,2569.5 363.51,2689.3 ; v2(363.51,2988.52) 363.51,2689.3 ; v2(410.49,565.4) 376.82,565.4 262.08,680.14 262.08,710.61 349.04,797.58 349.04,1140.28 538.76,1330 781.72,1330 937.9,1486.18 v2(1025.69,1486.18) 1025.69,1518.22 1115.84,1608.38 1206.29,1608.38 1270.81,1543.86 1962.31,1543.86 v2(1982.33,1563.88) 1982.33,1637.33 2031.86,1686.86 2119.87,1686.86 2131.85,1674.88 2131.85,1617.82 2208.38,1541.3 2781.48,1541.3 2844.79,1604.61 2925.61,1604.61 2962.26,1641.26 v2(2962.26,1750.28) ; v2(1043.12,2871.78) 996.65,2918.26 538.94,2918.26 485.86,2865.17 485.86,2746.67 428.49,2689.3 363.51,2689.3 ; v2(1359.02,1897.69) 1359.02,1884.11 1395.6,1847.53 1785.26,1847.53 1957.43,2019.69 v2(1957.43,2147.23)
  Bottom Layer w8.7: v2(410.49,565.4) 429.44,565.4 R224.1@446.82,582.78 ; v2(938.48,2316.6) 907.72,2316.6 869.93,2354.39 869.93,2480.45 889.98,2500.5 1020.38,2500.5 1076.73,2556.85 1076.73,2836.52 1071.63,2841.61 R108.2@1052.99,2841.61 1052.99,2861.91 v2(1043.12,2871.78) ; v2(1957.43,2147.23) 1957.54,2147.34 1987.47,2147.34 R25.2@1987.58,2147.45 ; v2(1982.33,1563.88) 1982.33,1561.36 1985.25,1558.44 1985.25,1557.07 2025.35,1516.97 R89.1@2097.01,1516.97 ; R60.1@3419.05,807.03 3419.05,893.42 v2(3434.04,908.41)
I2C_SCL_SPIB_CLK: U1.T21 U30.2 | length 2305.3
  Top Layer w6: 2150.54,2483.87 2162.14,2495.48 2162.14,2546.64 U1.T21@2171.89,2556.4
  Top Layer w7: v2(414.51,2958.37) 423.99,2967.84 U30.2@423.99,3003.35
  Top Layer w10.8: v2(1785.78,2462.16) 1821.89,2426.05 1998.97,2426.05 2045.34,2472.41 2139.08,2472.41 2150.54,2483.87
  Bottom Layer w6: v2(414.51,2958.37) 444.88,2928 599.34,2928 755.36,3084.02 1275.38,3084.02 1785.78,2573.61 v2(1785.78,2462.16)
I2C_SDA: J1.2 R29.2 R56.2 R59.1 R90.1 R98.1 R100.2 R102.2 R110.2 R111.2 R139.2 R160.2 R166.1 R197.1 R238.1 S5.1 U30.3 | length 10852.8
  Top Layer w7: U30.3@439.74,3003.35 439.74,2977.98 447.79,2969.93 v2(447.79,2969.77)
  Top Layer w8.7: R139.2@3033.12,1882.35 3033.12,1934.12 3065.16,1966.16 3148.93,1966.16 3198.37,1916.72 3198.37,1860.49 3377.17,1681.7 R56.2@3377.17,1641.74
  Top Layer w10.8: J1.2@158.07,2469.5 157.57,2470 107.1,2470 81.89,2495.21 81.89,2619.19 105.04,2642.34 210.08,2642.34 234.08,2618.33 R98.1@254.77,2618.33 R160.2@284.77,2618.33 ; v2(1381.2,818.08) 1381.2,862.6 1442.73,924.12 1518.85,924.12 1540.17,902.81 R100.2@1566.21,902.81 1583.62,902.81 1600.42,919.6 R102.2@1600.42,932.52 1600.42,1044.16 1500.93,1143.64 1471.08,1143.64 R197.1@1467.94,1146.78 1467.94,1193.68 1396.54,1265.08 S5.1@1396.54,1319.13 1397.01,1319.6 1397.01,1411.01 1732.19,1746.19 1732.19,2012.82 1743.37,2024 v2(1759.45,2024) 1854.44,1929 2263.11,1929 2425.89,2091.79 2686.32,2091.79 2702.54,2075.56 v2(2704.49,2075.56) 2704.27,2075.35 R111.2@2704.27,2052.59 ; v2(2892.81,1681.84) 2892.81,1742.67 2983.13,1832.99 2983.13,1862.23 3003.25,1882.35 R139.2@3033.12,1882.35
  L3_SIG1 w6: J1.2@158.07,2469.5 165.24,2469.5 233.43,2537.7 233.43,2971.62 291.34,3029.53 414.8,3029.53 447.79,2996.54 v2(447.79,2969.77) ; v2(2704.49,2075.56) 2704.49,2004.61 2877.84,1831.26 2877.84,1696.81 v2(2892.81,1681.84) 2911.94,1700.97 2962.69,1700.97 3079.46,1584.2 3264.09,1584.2 3402.21,1446.08 3402.21,958.62 v2(3383.7,940.1)
  L6_SIG2 w6: v2(447.79,2969.77) 467.01,2950.55 896.35,2950.55 v2(976.44,3030.64) ; v2(2151.68,1639.3) 2179.98,1611 2614.05,1611 2638.29,1586.76 2797.73,1586.76 v2(2892.81,1681.84)
  L6_SIG2 w8.7: v2(1033.45,830.23) 1060.54,857.32 1364.22,857.32 1381.2,840.34 v2(1381.2,818.08)
  Bottom Layer w8.7: R238.1@586.27,359.37 R166.1@586.27,324.37 591.31,329.42 950.93,329.42 1033.45,411.94 v2(1033.45,830.23) ; v2(976.44,3030.64) 972.26,3026.46 R110.2@972.26,3003.85 1070.15,3003.85 1791.43,2282.57 1791.43,2141.97 1825.34,2108.06 R29.2@1825.34,2066.72 1802.16,2066.72 v2(1759.45,2024) ; R90.1@2131.92,1609.83 2132.08,1610 2132.08,1622.17 2149.21,1639.3 v2(2151.68,1639.3) ; v2(3383.7,940.1) 3384.38,939.42 R59.1@3384.38,807.03
I2C_SDA_SPIB_MOSI: U1.R20 U30.5 | length 2357.2
  Top Layer w6: 2168.57,2467.29 2178.14,2476.86 2197.17,2495.88 2197.17,2570.49 U1.R20@2191.58,2576.08
  Top Layer w10.8: U30.5@479.11,3011.22 487.96,3011.22 503.04,2996.13 503.04,2986.77 v2(504.42,2985.39) ; v2(1784.7,2425.86) 1810.56,2400 2045.03,2400 2071.61,2426.58 2127.87,2426.58 2168.57,2467.29
  Bottom Layer w6: v2(504.42,2985.39) 599.39,2985.39 732.73,3118.73 1294.04,3118.73 1820,2592.77 1820,2461 1784.86,2425.86 v2(1784.7,2425.86)
JTAG_TDO: R93.2 U1.Y15 | length 754.6
  Top Layer w4: 2019.74,2682.1 2026.57,2675.27 2092.39,2675.27 U1.Y15@2093.15,2674.51
  Top Layer w10.8: R93.2@1506.76,2422.23 1506.76,2513.26 1680.5,2687 2014.84,2687 2019.74,2682.1
LIN_BUS: C132.1 J4.3 R21.1 U23.6 | length 258.7
  Top Layer w17: 281.35,836.32 U23.6@316.77,836.32
  Top Layer w20: R21.1@256.77,933.21 R21.1@258.07,934.5
  Top Layer w24: J4.3@158.07,934.5 R21.1@258.07,934.5 ; R21.1@256.77,933.21 C132.1@256.77,836.32 281.35,836.32
LIN_PHY_EN: R17.1 R88.2 U23.2 | length 92
  Top Layer w10.8: U23.2@419.13,810.73 R17.1@479.13,810.73 R88.2@479.13,778.73
LIN_PHY_EN_CTRL: R88.1 S4.2 | length 1245.6
  Top Layer w10.8: R88.1@519.49,778.31 519.49,763.77 v2(528.96,754.3) ; v2(1429.48,661.24) 1561.51,529.21 S4.2@1561.51,496.87
  L6_SIG2 w6: v2(528.96,754.3) 631.94,754.3 795.4,590.84 1173.84,590.84 1245.76,662.76 1427.97,662.76 v2(1429.48,661.24)
LIN_PHY_RX: R18.1 R22.1 U24.1 | length 2352.7
  Top Layer w10.8: R22.1@497.04,709.34 R18.1@497.04,743.84 ; R22.1@497.07,709.3 v2(523.52,709.27) ; v2(565.44,2871.3) 565.44,2872.76 583.97,2891.29 583.97,2911.91 U24.1@584.32,2912.26
  L3_SIG1 w6: v2(523.52,709.27) 484.13,748.66 484.13,1839.72 538.09,1893.67 538.09,2115.78 500.87,2153 500.87,2370.63 555.64,2425.4 555.64,2861.51 v2(565.44,2871.3)
LIN_PHY_RX_UARTB_TX: U1.AA17 U24.9 | length 2003.6
  Top Layer w8: v2(2006.99,2629.81) 2008.91,2631.72 2015.69,2631.72 2026.38,2642.4 2054.01,2642.4 2061.28,2635.14 U1.AA17@2073.47,2635.14
  Top Layer w10.8: v2(599.79,3134.61) 604.01,3130.39 U24.9@604.01,3087.46
  L6_SIG2 w6: v2(599.79,3134.61) 629.41,3104.99 1249.63,3104.99 1489.78,2864.84 v2(1489.78,2767.46) 1666.68,2767.46 1738.93,2839.71 1967.27,2839.71 1982.53,2824.45 1982.53,2785.13 2063.86,2703.8 2063.86,2686.67 v2(2006.99,2629.81)
LIN_PHY_TX: R19.1 U24.3 | length 2129.5
  Top Layer w10.8: R19.1@499.49,861.92 499.49,877.82 v2(508.29,886.63) ; v2(623.03,2863.19) 623.5,2863.66 623.5,2912.07 U24.3@623.69,2912.26
  L3_SIG1 w6: v2(508.29,886.63) 508.29,1835.79 552.5,1880 552.5,2135.26 519.08,2168.67 519.08,2360.09 584.43,2425.43 584.43,2802.19 623.03,2840.8 v2(623.03,2863.19)
LIN_PHY_TX_UARTB_RX: U1.Y18 U24.6 | length 1901.3
  Top Layer w4: v2(2039.05,2614.63) 2039.84,2615.42 U1.Y18@2093.15,2615.45
  Top Layer w10.8: U24.6@663.06,3087.46 663.06,3118.19 v2(671.23,3126.35)
  L6_SIG2 w6: v2(671.23,3126.35) 1265.79,3126.35 1532.09,2860.05 2052.06,2860.05 2127.77,2784.34 2127.77,2732.07 2117.85,2722.15 2117.85,2693.42 v2(2039.05,2614.63)
LIN_VDD: C123.1 D8.2 R31.2 R32.2 U23.7 | length 552.5
  Top Layer w15: 355.67,810.73 356.73,811.79
  Top Layer w17: U23.7@316.77,810.73 355.67,810.73
  Top Layer w20: R31.2@306.06,1134.5 R32.2@306.06,1034.5 345.85,1034.5 369.9,1010.45 C123.1@369.9,937.13 369.9,824.97 356.73,811.79
  Bottom Layer w20: v2(369.03,893.27) 404.26,893.27 437.98,859.56 D8.2@437.98,808.26
LVDS_VALID: R257.2 TP3.1 | length 36.5
  Top Layer w10.8: R257.2@2576.93,1988.65 TP3.1@2576.93,2025.16
MCU_3V3: C119.1 J11.1 R154.1
MCU_5V: C120.1 J11.2 R155.1
  other v2: 761.96,1414.46 789.6,1414.57 817.23,1414.67 773.41,1435.99 801.74,1435.75
MCU_SOP0: J12.19 R235.2 | length 2233
  Top Layer w10.8: R235.2@390.05,674.49 390.17,674.37 414.94,674.37 v2(415.17,674.61)
  L3_SIG1 w6: v2(415.17,674.61) 415.17,631.76 693.22,353.71 1387.63,353.71 1520.5,220.83 1845.82,220.83 2062.15,437.16 2111.8,437.16 v2(2129.44,419.52)
  Bottom Layer w8.7: v2(2129.44,419.52) 2191.92,482 J12.19@2287.05,482
MCU_SOP1: J12.17 R244.2 | length 1672
  Top Layer w10.8: v2(894.38,271.65) 894.9,272.17 R244.2@894.9,337.37
  L6_SIG2 w6: v2(894.38,271.65) 977.62,188.41 1838.03,188.41 2181.28,531.66 v2(2182.79,531.66)
  Bottom Layer w8.7: v2(2182.79,531.66) 2263.79,531.66 2287.05,554.92 J12.17@2287.05,582
MUX_CTRL_FTDI_DCA_LP_UARTA: R95.1 S1.6 U16.7 U16.8 | length 2550.7
  Top Layer w8: 1214.07,2002.98 1214.65,2002.4
  Top Layer w10.8: v2(276.25,3431.28) 296.89,3451.92 S1.6@296.89,3639.18 ; v2(1196.88,1895.79) 1196.88,1897.74 1194.68,1899.94 1194.68,1916.18 1194.77,1916.27 1194.77,1937.66 U16.8@1194.96,1937.85 1194.96,1983.88 1214.07,2002.98 ; U16.7@1214.65,1937.85 1214.65,2002.4 1245.08,2002.4 1256.51,2013.83 R95.1@1256.51,2026.17
  L3_SIG1 w6: v2(276.25,3431.28) 365.03,3342.51 544.42,3342.51 755.36,3131.57 755.36,2740.99 920,2576.34 920,2398.8 996.35,2322.45 996.35,2230.13 1131.44,2095.05 1131.44,1883.32 1149.2,1865.56 1168.77,1865.56 1196.88,1893.67 v2(1196.88,1895.79)
MUX_CTRL_FTDI_DCA_RS232: R7.1 S1.3 U12.16 | length 1295.9
  Top Layer w10.8: v2(440.39,3459.09) 440.39,3492.59 446.89,3499.09 S1.3@446.89,3639.18 ; U12.16@767.33,2635.52 767.33,2669.7 752.22,2684.8 752.22,2727.24 774.77,2749.79 v2(776.23,2749.79)
  L3_SIG1 w6: v2(440.39,3459.09) 467.12,3432.35 626.17,3432.35 798.17,3260.35 798.17,2954.99 824.8,2928.36 824.8,2798.37 v2(776.23,2749.79)
MUX_CTRL_FTDI_DCA_SPIA: R12.2 S4.3 U28.14 U28.24 | length 2903.7
  Top Layer w10.8: S4.3@1611.51,496.87 1611.51,541.39 1641.12,570.99 1748.09,570.99 1778.49,540.59 1820.8,540.59 v2(1830.7,530.68)
  L3_SIG1 w6: v2(3014.46,1456.56) 3097.23,1456.56 3213.52,1340.27 3213.52,1212.23 3191.26,1189.97 3166.58,1189.97 3160.37,1196.18 v2(3132.45,1196.18)
  L6_SIG2 w6: v2(1830.7,530.68) 1830.7,550.7 2202.2,922.2 2346.59,922.2 2693.73,1269.34 2911.35,1269.34 2925.74,1254.95 3061.39,1254.95 3120.17,1196.18 v2(3132.45,1196.18)
  Bottom Layer w8.7: v2(3014.46,1456.56) 3024.42,1446.6 R12.2@3024.42,1408.15 3038.74,1408.15 3045.05,1414.47 U28.24@3045.05,1465.05 ; v2(3132.45,1196.18) 3180.43,1196.18 3300.96,1316.7 U28.14@3300.96,1465.05
MUX_CTRL_LIN_UARTB: R253.1 S4.5 U24.7 U24.8 | length 3417.4
  Top Layer w10.8: U24.8@623.69,3087.46 623.69,3127.27 634.79,3138.37 ; U24.7@643.38,3087.46 643.38,3129.78 634.79,3138.37 ; v2(698.52,3151.47) 678.97,3171.01 R253.1@655.04,3171.01 655.04,3158.63 634.79,3138.37 ; S4.5@1711.51,496.87 v2(1711.48,548.59)
  L3_SIG1 w6: v2(698.52,3151.47) 735,3114.98 735,2740.18 899,2576.18 899,2505.22 873.79,2480.01 873.79,2421.83 982.4,2313.23 982.4,2214.6 1111.3,2085.7 1111.3,1973.18 1009.01,1870.89 1009.01,1567.1 1205,1371.12 1205,1089.03 1324.55,969.49 1324.55,907.45 1419.75,812.25 1479.54,812.25 1664.49,627.31 1664.49,595.59 v2(1711.48,548.59)
MUX_CTRL_SPIB_I2C_SYS_RST_HOST_CLK_REQ: R271.1 S4.6 U30.15 | length 4147.2
  Top Layer w7: 348.26,3019.56 355.67,3026.97 U30.15@384.62,3026.97
  Top Layer w10.8: v2(288.35,2963.63) 297.44,2972.73 329.29,2972.73 340.85,2984.29 340.85,3012.15 348.26,3019.56 ; S4.6@1761.51,496.87 1766.86,491.52 v2(1796.26,491.52)
  L3_SIG1 w6: v2(288.35,2963.63) 378.45,2873.53 378.45,953.62 347.78,922.96 347.78,871.78 376.5,843.07 376.5,626.26 v2(403.24,599.52)
  L6_SIG2 w6: v2(403.24,599.52) 489.48,599.52 637.09,451.91 1063.94,451.91 1140.85,375 1437.79,375 1554.32,491.52 v2(1796.26,491.52)
MUX_CTRL_UARTA_CAN_FD: R128.1 S1.4 U18.8 | length 1851.9
  Top Layer w10.8: v2(373.82,3467.44) 396.89,3490.51 S1.4@396.89,3639.18 ; U18.8@1300.04,2541.56 1300.04,2504.05 1306.31,2497.78 R128.1@1306.31,2480.4 1320.46,2480.4 1323.95,2483.9 v2(1325.9,2483.9)
  L3_SIG1 w6: v2(373.82,3467.44) 406.44,3500.06 498.96,3500.06 535.43,3463.58 647.64,3463.58 888.26,3222.97 888.26,2989.9 1000.93,2877.23 1000.93,2769.95 1286.98,2483.9 v2(1325.9,2483.9)
MUX_CTRL_XDS_DCA_JTAG: R5.1 S4.4 U4.15 | length 2512.1
  Top Layer w7: U4.15@1461.61,1874.02 1461.61,1858.26 1470.17,1849.71
  Top Layer w10.8: v2(1468.59,1826.95) 1480.87,1826.95 1487.66,1833.75 1483.22,1838.19 1479.83,1838.19 1470.17,1847.85 1470.17,1849.71 ; S4.4@1661.51,496.87 1661.51,463.88 1680.75,444.64 1795.81,444.64 1879.46,528.29 v2(1879.46,571.55)
  L3_SIG1 w6: v2(1468.59,1826.95) 1491.95,1826.95 1522.55,1857.55 1522.55,1878.47 1512.24,1888.78 1478.54,1888.78 1434.11,1844.36 1434.11,1804.22 1425.39,1795.5 1425.39,1560.99 1638.69,1347.69 1711.63,1347.69 2168.33,890.99 2168.33,662.07 2030.74,524.49 1926.52,524.49 v2(1879.46,571.55)
MUX_CTRL_XDS_DCA_LP_FTDI_UARTA: R8.1 S1.5 U12.8 | length 1772.5
  Top Layer w10.8: v2(332.77,3439.89) 346.89,3454.01 S1.5@346.89,3639.18 ; R8.1@940.58,2346.78 946.46,2352.65 U12.8@946.46,2403.24 946.46,2438.67 v2(945.37,2439.76)
  L3_SIG1 w6: v2(332.77,3439.89) 388.49,3439.89 429.84,3481.24 476.43,3481.24 509.84,3447.84 637.8,3447.84 847.59,3238.04 847.59,2974.06 937.41,2884.24 937.41,2518.09 945.37,2510.13 v2(945.37,2439.76)
MUX_CTRL_XDS_FTDI_DCA_LP_RS232: R127.1 S1.2 U18.16 | length 1123.8
  Top Layer w10.8: S1.2@496.89,3639.18 496.89,3553.68 1120.73,2929.84 R127.1@1120.73,2832.5 1120.73,2774.02 U18.16@1120.91,2773.84
NetC37_2: C37.2 R69.1 R266.2 U5.3 | length 226
  Top Layer w15: U5.3@513.63,2069.65 558.51,2069.65 570.72,2081.85 C37.2@640.72,2081.85 R69.1@690.72,2081.85 734.26,2081.85 R266.2@734.45,2081.66
NetC39_2: C39.2 R68.1 R79.2 | length 358.5
  Top Layer w10.8: v2@266.37,2154.18 274.18,2146.37 R79.2@274.18,2121.22 ; R68.1@274.18,1992.48 C39.2@274.18,1947.48 294.13,1947.48 v2@307.98,1933.64
  L3_SIG1 w6: v2(266.66,2154.18) 308.27,2112.57 v2(308.27,1933.64)
NetC43_1: C43.1 D2.1 L1.1
NetC68_1: C68.1 U14.11 | length 76.8
  Top Layer w7: 3159.04,664.96 U14.11@3159.04,709.79
  Top Layer w10.8: 3159.04,664.96 3175.93,648.07 C68.1@3175.93,640.03
NetC69_1: C69.1 U15.7 | length 86.6
  Top Layer w10.8: C69.1@2080.38,1294.85 2080.38,1309.17 2096.86,1325.64 2113.47,1325.64 2129.53,1341.71 U15.7@2139.19,1341.71
NetC94_1: C94.1 R169.1 U21.96 | length 111.9
  Bottom Layer w8: U21.96@1591.66,1695.23 1625.87,1695.23
  Bottom Layer w8.7: 1625.87,1695.23 1639.64,1681.45 C94.1@1639.64,1658.28 R169.1@1674.64,1658.28
NetC95_2: C95.2 R202.2 U21.68 | length 134.3
  Bottom Layer w6: U21.68@1591.66,2136.17 1639.83,2136.17
  Bottom Layer w8.7: 1639.83,2136.17 1652.16,2148.5 1656.1,2148.5 1663.56,2155.96 C95.2@1663.56,2159.9 1680.78,2159.9 1694.35,2146.32 R202.2@1708.21,2146.32
NetC97_2: C97.2 U21.89 Y2.3 | length 154.3
  Bottom Layer w8: U21.89@1591.66,1805.46 1624.93,1805.46
  Bottom Layer w8.7: 1624.93,1805.46 1631.92,1805.46 1645.14,1792.25 1680.15,1792.25 C97.2@1681.09,1791.31 1713.08,1791.31 1729.37,1775.02 Y2.3@1729.37,1771.08
NetC98_2: C98.2 U21.88 Y2.1 | length 257.3
  Bottom Layer w8: U21.88@1591.66,1821.21 1650.7,1821.21
  Bottom Layer w8.7: 1650.7,1821.21 1662.63,1833.14 C98.2@1681.09,1833.14 1681.09,1831.17 1693.89,1818.37 1788.63,1818.37 1800.24,1829.98 Y2.1@1800.24,1861.63
NetC110_2: C110.2 R129.1 U19.3 | length 108.8
  Top Layer w8.7: U19.3@570.55,1670.14 630.06,1670.14 C110.2@632.96,1667.24 R129.1@632.96,1712.44
NetC111_2: C111.2 R130.1 R140.2 | length 322
  Top Layer w10.8: v2(243.99,1728.05) 243.99,1727.19 261.67,1709.51 R140.2@274.01,1709.51 ; R130.1@274.01,1580.77 C111.2@274.01,1535.77 292.8,1535.77 v2(301.87,1544.84)
  L3_SIG1 w6: v2(243.99,1728.05) 301.87,1670.18 v2(301.87,1544.84)
NetC112_2: C112.2 P1.2 U20.5 | length 136.2
  Top Layer w16: P1.2@272.13,2254.41 C112.2@358.31,2254.41 U20.5@408.31,2254.41
NetC158_1: C158.1 R259.1 U29.6 | length 23.5
  Top Layer w12: 3747.87,1645.53 U29.6@3771.39,1645.53
NetD1_2: D1.2 L9.2
NetD3_1: D3.1 Q2.3 | length 40
  Top Layer w10.8: Q2.3@1966.97,695.23 D3.1@1966.97,735.23
NetD3_2: D3.2 R172.1 | length 50
  Top Layer w10.8: D3.2@2024.05,735.23 R172.1@2024.05,785.23
NetD4_1: D4.1 R87.2 | length 60.6
  Top Layer w10.8: D4.1@1736.5,949.27 1796.06,949.27 R87.2@1796.8,948.53
NetD5_1: D5.1 Q1.3 | length 30
  Top Layer w10.8: D5.1@1753.99,401.58 Q1.3@1783.99,401.58
NetD5_2: D5.2 R141.1 | length 40
  Top Layer w10.8: R141.1@1656.91,401.58 D5.2@1696.91,401.58
NetD6_2: D6.2 R174.2 | length 51
  Top Layer w8: D6.2@2761.17,481.47 D6.2@2761.5,481.14
  Top Layer w12: R174.2@2711,481 2711.14,481.14 D6.2@2761.5,481.14
NetD7_1: D7.1 Q4.3 | length 30
  Top Layer w10.8: D7.1@1009.59,410.73 Q4.3@1039.59,410.73
NetD7_2: D7.2 R28.1 | length 60.9
  Top Layer w10.8: D7.2@952.51,410.73 952.51,405.61 R28.1@991.94,366.18
NetD8_1: D8.1 R21.2 | length 143
  Top Layer w15: v2(293.31,905.58) 305.31,917.58 R21.2@305.31,934.5
  Bottom Layer w15: D8.1@264.75,808.26 264.75,877.01 v2(293.31,905.58)
NetD9_2: D9.2 R64.1 | length 35
  Top Layer w10.8: D9.2@483.11,2729.64 R64.1@518.11,2729.64
NetD10_2: D10.2 R252.2 | length 208.1
  Top Layer w10.8: D10.2@2005.27,834.24 v2(2034.9,834.24)
  L3_SIG1 w6: v2(1938.42,925.19) 1965.17,925.19 2034.9,855.46 v2(2034.9,834.24)
  Bottom Layer w8.7: v2(1938.42,925.19) 1948.76,914.85 R252.2@1948.76,897.64
NetD11_1: D11.1 Q3.3 | length 38.1
  Top Layer w10.8: Q3.3@3032.98,426.62 3032.98,464.24 D11.1@3033.15,464.41
  Top Layer w15: Q3.3@3032.98,426.62 Q3.3@3033.15,426.79
NetD11_2: D11.2 R258.1 | length 30
  Top Layer w12: R258.1@2946.06,464.41 D11.2@2976.06,464.41
NetD12_2: D12.2 L8.2
NetD13_2: D13.2 R287.1 | length 50
  Top Layer w10.8: R287.1@1056.3,685.39 D13.2@1106.3,685.39
NetJ6_4: J6.4 R34.1 | length 96.3
  Bottom Layer w8.7: R34.1@2881.65,260.03 2896.95,260.03 2911.94,275.02 J6.4@2911.94,334.85
NetJ6_5: J6.5 R37.2 | length 201.4
  Bottom Layer w8.7: R37.2@2838.5,723.28 2838.5,708.31 2931.62,615.18 J6.5@2931.62,560.44
NetJ6_6: J6.6 R38.1 | length 145.6
  Bottom Layer w8.7: R38.1@2881.05,225.06 2906.47,225.06 2915.38,233.97 2915.38,249.94 2931.62,266.19 J6.6@2931.62,334.85
NetJ6_7: J6.7 R39.2 | length 193.3
  Bottom Layer w8.7: R39.2@2875.7,722.4 2875.7,699.71 2951.31,624.1 J6.7@2951.31,560.44
NetJ6_8: J6.8 R40.1 | length 85
  Bottom Layer w8.7: R40.1@2951.31,249.85 J6.8@2951.31,334.85
NetJ6_9: J6.9 R41.2 | length 186.2
  Bottom Layer w8.7: R41.2@2912.47,722.4 2912.47,691.31 2970.99,632.78 J6.9@2970.99,560.44
NetJ6_10: J6.10 R42.1 | length 145.6
  Bottom Layer w8.7: J6.10@2970.99,334.85 2970.99,266.19 2987.24,249.94 2987.24,233.97 2996.15,225.06 R42.1@3021.57,225.06
NetJ6_11: J6.11 R52.2 | length 180.3
  Bottom Layer w8.7: R52.2@2947.46,722.84 2947.46,683.42 2990.68,640.21 J6.11@2990.68,560.44
NetJ6_12: J6.12 R53.1 | length 95.8
  Bottom Layer w8.7: J6.12@2990.68,334.85 2990.68,275.9 3006.55,260.03 R53.1@3020.97,260.03
NetJ6_13: J6.13 R58.2 | length 183.7
  Bottom Layer w8.7: R58.2@2981.57,721.31 3000.19,721.31 3010.36,711.13 J6.13@3010.36,560.44
NetJ6_26: J6.26 R219.1 | length 72.7
  Bottom Layer w5.9: R219.1@3123.48,268.42 3123.97,268.42 3133.17,277.62 3133.17,290.96 3128.48,295.66 J6.26@3128.48,334.85
NetJ6_28: J6.28 R220.1 | length 72.9
  Bottom Layer w5.9: J6.28@3148.16,334.85 3148.16,295.66 3142.97,290.47 3142.97,277.62 3152.18,268.42 R220.1@3152.67,268.42
NetJ6_44: J6.44 R225.1 | length 150.4
  Bottom Layer w5.9: R225.1@3276.61,247.17 3276.61,246.68 3286.06,237.23 3304.93,237.23 3310.58,242.88 3310.58,255.25 3307.13,258.7 3302.06,258.7 3298.6,262.16 3298.6,269.03 3302.06,272.48 3306.77,272.48 3310.58,276.29 3310.58,290.72 3305.64,295.66 J6.44@3305.64,334.85
NetJ6_46: J6.46 R226.1 | length 151
  Bottom Layer w5.9: R226.1@3276.61,217.48 3276.61,217.98 3286.06,227.43 3308.98,227.43 3320.38,238.82 3320.38,290.72 3325.33,295.66 J6.46@3325.33,334.85
NetJ6_50: J6.50 R227.1 | length 72.9
  Bottom Layer w5.9: R227.1@3359.7,268.42 3360.19,268.42 3369.64,277.87 3369.64,290.72 3364.7,295.66 J6.50@3364.7,334.85
NetJ6_51: J6.51 R59.2 | length 206.2
  Bottom Layer w8.7: J6.51@3384.38,560.44 R59.2@3384.38,766.68
NetJ6_52: J6.52 R228.1 | length 72.9
  Bottom Layer w5.9: J6.52@3384.38,334.85 3384.38,295.66 3379.44,290.72 3379.44,277.87 3388.89,268.42 R228.1@3389.38,268.42
NetJ6_53: J6.53 R60.2 | length 212.4
  Bottom Layer w8.7: J6.53@3404.07,560.44 3404.07,722.14 3419.05,737.12 R60.2@3419.05,766.68
NetJ6_55: J6.55 R61.2 R152.1 | length 255.6
  Bottom Layer w8.7: J6.55@3423.75,560.44 3423.75,705.4 3458.35,740 R61.2@3458.35,770.02 3489.35,770.02 R152.1@3489.84,770.51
